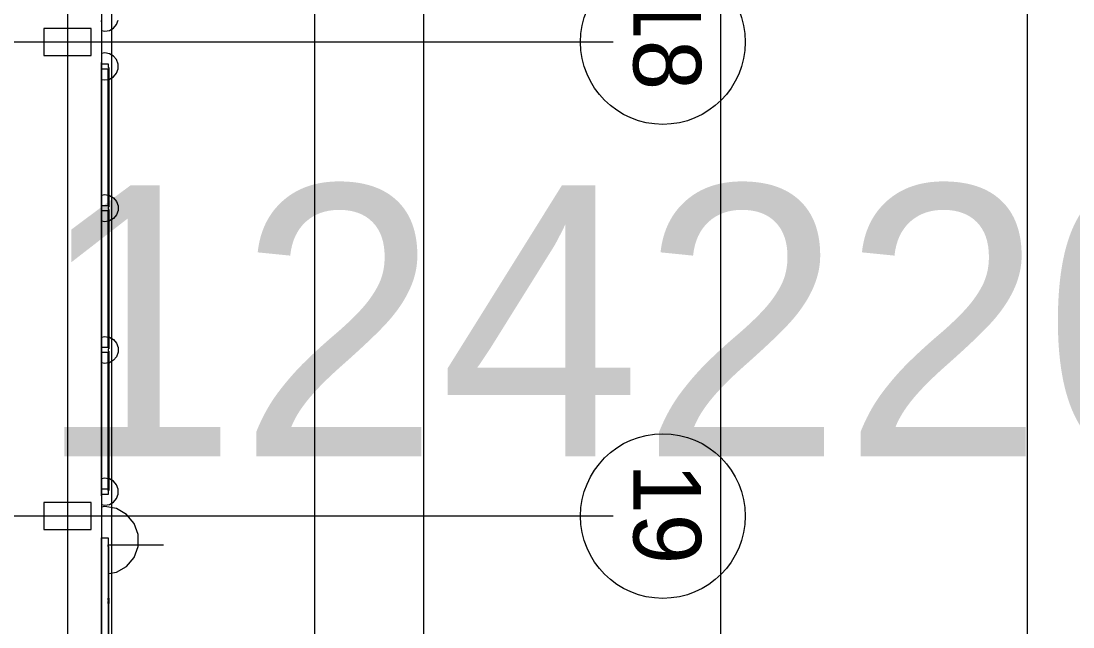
# Model space of a CAD drawing. Extents: x -264165 to -263575, y -1242333 to -1242036.
# Drawn here: x -263796.23 to -263780.69, y -1242204.52 to -1242195.57 of the extents above; entities that cross this region are included whole.
import ezdxf

# ---------------------------------------------------------------- set-up
doc = ezdxf.new("R2010")
doc.units = 0
for name, color, linetype in [('KFA_HEKT_SIET_1-1000', 7, 'Continuous'), ('KFA_HESCON_OSI_STAVBY', 7, 'Continuous'), ('KFA_SITUACIA_DRS_VYTYCOVAK_SEDA', 7, 'Continuous')]:
    doc.layers.add(name, color=color, linetype=linetype)

msp = doc.modelspace()

# ---------------------------------------------------------------- linework, layer by layer
at = {"layer": 'KFA_HESCON_OSI_STAVBY'}
for p, q in [((-263795.543, -1242080.447), (-263795.543, -1242248.737)), ((-263787.486, -1242195.882), (-263921.823, -1242195.882)), ((-263787.486, -1242195.882), (-263787.486, -1242195.882)), ((-263787.486, -1242202.882), (-263921.823, -1242202.882)), ((-263787.486, -1242202.882), (-263787.486, -1242202.882))]:
    msp.add_line(p, q, dxfattribs=at)
for centre in [(-263786.751, -1242195.882), (-263786.751, -1242202.882)]:
    msp.add_circle(centre, 1.216, dxfattribs=at)
at = {"layer": 'KFA_SITUACIA_DRS_VYTYCOVAK_SEDA'}
for p, q in [((-263781.364, -1242208.936), (-263781.371, -1242084.903)), ((-263781.364, -1242208.936), (-263781.371, -1242084.903)), ((-263785.893, -1242228.625), (-263785.893, -1242090.308)), ((-263791.893, -1242228.625), (-263791.893, -1242100.14)), ((-263790.279, -1242228.625), (-263790.279, -1242100.14)), ((-263794.893, -1242101.382), (-263794.893, -1242227.382)), ((-263795.043, -1242188.882), (-263795.043, -1242195.882)), ((-263795.043, -1242188.882), (-263795.043, -1242195.882)), ((-263795.043, -1242195.582), (-263795.043, -1242195.562)), ((-263795.043, -1242195.582), (-263795.043, -1242195.562)), ((-263795.043, -1242195.582), (-263795.043, -1242196.182)), ((-263795.043, -1242195.582), (-263795.043, -1242196.182)), ((-263794.82, -1242195.622), (-263794.796, -1242195.557)), ((-263794.82, -1242195.622), (-263794.796, -1242195.557)), ((-263795.193, -1242195.682), (-263795.893, -1242195.682)), ((-263795.193, -1242195.682), (-263795.893, -1242195.682)), ((-263795.893, -1242195.682), (-263795.893, -1242195.882)), ((-263795.893, -1242195.682), (-263795.893, -1242195.882)), ((-263795.193, -1242195.882), (-263795.193, -1242195.682)), ((-263795.193, -1242195.882), (-263795.193, -1242195.682)), ((-263795.193, -1242195.882), (-263795.193, -1242195.682)), ((-263795.193, -1242195.882), (-263795.193, -1242195.682)), ((-263795.043, -1242195.713), (-263794.993, -1242195.722)), ((-263795.043, -1242195.713), (-263794.993, -1242195.722)), ((-263794.993, -1242195.722), (-263794.924, -1242195.71)), ((-263794.993, -1242195.722), (-263794.924, -1242195.71)), ((-263794.924, -1242195.71), (-263794.864, -1242195.675)), ((-263794.924, -1242195.71), (-263794.864, -1242195.675)), ((-263794.864, -1242195.675), (-263794.82, -1242195.622)), ((-263794.864, -1242195.675), (-263794.82, -1242195.622)), ((-263795.893, -1242195.882), (-263795.893, -1242196.082)), ((-263795.893, -1242195.882), (-263795.893, -1242196.082)), ((-263795.193, -1242196.082), (-263795.193, -1242195.882)), ((-263795.193, -1242196.082), (-263795.193, -1242195.882)), ((-263795.193, -1242196.082), (-263795.193, -1242195.882)), ((-263795.193, -1242196.082), (-263795.193, -1242195.882)), ((-263795.043, -1242195.882), (-263795.043, -1242202.882)), ((-263795.043, -1242195.882), (-263795.043, -1242202.882)), ((-263795.893, -1242196.082), (-263795.193, -1242196.082)), ((-263795.893, -1242196.082), (-263795.193, -1242196.082)), ((-263794.993, -1242196.042), (-263795.043, -1242196.051)), ((-263794.993, -1242196.042), (-263795.043, -1242196.051)), ((-263794.924, -1242196.054), (-263794.993, -1242196.042)), ((-263794.924, -1242196.054), (-263794.993, -1242196.042)), ((-263794.864, -1242196.089), (-263794.924, -1242196.054)), ((-263794.864, -1242196.089), (-263794.924, -1242196.054)), ((-263795.043, -1242196.202), (-263795.043, -1242196.182)), ((-263795.043, -1242196.202), (-263795.043, -1242196.182)), ((-263795.043, -1242196.282), (-263795.043, -1242196.202)), ((-263795.043, -1242196.282), (-263795.043, -1242196.202)), ((-263795.043, -1242196.202), (-263794.943, -1242196.202)), ((-263795.043, -1242196.202), (-263794.943, -1242196.202)), ((-263794.943, -1242196.202), (-263794.943, -1242196.259)), ((-263794.943, -1242196.202), (-263794.943, -1242196.259)), ((-263794.82, -1242196.142), (-263794.864, -1242196.089)), ((-263794.82, -1242196.142), (-263794.864, -1242196.089)), ((-263794.796, -1242196.207), (-263794.82, -1242196.142)), ((-263794.796, -1242196.207), (-263794.82, -1242196.142)), ((-263794.796, -1242196.277), (-263794.796, -1242196.207)), ((-263794.796, -1242196.277), (-263794.796, -1242196.207)), ((-263795.043, -1242198.296), (-263795.043, -1242196.282)), ((-263795.043, -1242198.296), (-263795.043, -1242196.282)), ((-263794.943, -1242196.282), (-263795.043, -1242196.282)), ((-263794.943, -1242196.282), (-263795.043, -1242196.282)), ((-263794.933, -1242196.259), (-263794.943, -1242196.259)), ((-263794.933, -1242196.259), (-263794.943, -1242196.259)), ((-263794.943, -1242198.296), (-263794.943, -1242196.282)), ((-263794.943, -1242198.296), (-263794.943, -1242196.282)), ((-263794.933, -1242196.259), (-263794.933, -1242198.318)), ((-263794.933, -1242196.259), (-263794.933, -1242198.318)), ((-263794.924, -1242196.43), (-263794.864, -1242196.395)), ((-263794.924, -1242196.43), (-263794.864, -1242196.395)), ((-263794.864, -1242196.395), (-263794.82, -1242196.342)), ((-263794.864, -1242196.395), (-263794.82, -1242196.342)), ((-263794.82, -1242196.342), (-263794.796, -1242196.277)), ((-263794.82, -1242196.342), (-263794.796, -1242196.277)), ((-263795.043, -1242196.433), (-263794.993, -1242196.442)), ((-263795.043, -1242196.433), (-263794.993, -1242196.442)), ((-263794.993, -1242196.442), (-263794.943, -1242196.433)), ((-263794.993, -1242196.442), (-263794.943, -1242196.433)), ((-263794.933, -1242196.432), (-263794.924, -1242196.43)), ((-263794.933, -1242196.432), (-263794.924, -1242196.43)), ((-263795.043, -1242198.144), (-263794.993, -1242198.136)), ((-263795.043, -1242198.144), (-263794.993, -1242198.136)), ((-263794.993, -1242198.136), (-263794.943, -1242198.144)), ((-263794.993, -1242198.136), (-263794.943, -1242198.144)), ((-263794.933, -1242198.146), (-263794.924, -1242198.148)), ((-263794.933, -1242198.146), (-263794.924, -1242198.148)), ((-263794.924, -1242198.148), (-263794.864, -1242198.182)), ((-263794.924, -1242198.148), (-263794.864, -1242198.182)), ((-263794.864, -1242198.182), (-263794.82, -1242198.236)), ((-263794.864, -1242198.182), (-263794.82, -1242198.236)), ((-263794.82, -1242198.236), (-263794.796, -1242198.301)), ((-263794.82, -1242198.236), (-263794.796, -1242198.301)), ((-263795.043, -1242198.376), (-263795.043, -1242198.296)), ((-263795.043, -1242198.376), (-263795.043, -1242198.296)), ((-263795.043, -1242198.296), (-263794.943, -1242198.296)), ((-263795.043, -1242198.296), (-263794.943, -1242198.296)), ((-263795.043, -1242200.389), (-263795.043, -1242198.376)), ((-263795.043, -1242200.389), (-263795.043, -1242198.376)), ((-263794.943, -1242198.376), (-263795.043, -1242198.376)), ((-263794.943, -1242198.376), (-263795.043, -1242198.376)), ((-263794.933, -1242198.318), (-263794.943, -1242198.318)), ((-263794.933, -1242198.318), (-263794.943, -1242198.318)), ((-263794.943, -1242198.318), (-263794.943, -1242198.353)), ((-263794.943, -1242198.318), (-263794.943, -1242198.353)), ((-263794.933, -1242198.353), (-263794.943, -1242198.353)), ((-263794.933, -1242198.353), (-263794.943, -1242198.353)), ((-263794.943, -1242200.389), (-263794.943, -1242198.376)), ((-263794.943, -1242200.389), (-263794.943, -1242198.376)), ((-263794.933, -1242198.353), (-263794.933, -1242200.412)), ((-263794.933, -1242198.353), (-263794.933, -1242200.412)), ((-263794.796, -1242198.37), (-263794.82, -1242198.436)), ((-263794.796, -1242198.37), (-263794.82, -1242198.436)), ((-263794.796, -1242198.301), (-263794.796, -1242198.37)), ((-263794.796, -1242198.301), (-263794.796, -1242198.37)), ((-263794.993, -1242198.536), (-263795.043, -1242198.527)), ((-263794.993, -1242198.536), (-263795.043, -1242198.527)), ((-263794.943, -1242198.527), (-263794.993, -1242198.536)), ((-263794.943, -1242198.527), (-263794.993, -1242198.536)), ((-263794.924, -1242198.523), (-263794.933, -1242198.525)), ((-263794.924, -1242198.523), (-263794.933, -1242198.525)), ((-263794.864, -1242198.489), (-263794.924, -1242198.523)), ((-263794.864, -1242198.489), (-263794.924, -1242198.523)), ((-263794.82, -1242198.436), (-263794.864, -1242198.489)), ((-263794.82, -1242198.436), (-263794.864, -1242198.489)), ((-263795.043, -1242200.238), (-263794.993, -1242200.229)), ((-263795.043, -1242200.238), (-263794.993, -1242200.229)), ((-263794.993, -1242200.229), (-263794.943, -1242200.238)), ((-263794.993, -1242200.229), (-263794.943, -1242200.238)), ((-263794.933, -1242200.239), (-263794.924, -1242200.241)), ((-263794.933, -1242200.239), (-263794.924, -1242200.241)), ((-263794.924, -1242200.241), (-263794.864, -1242200.276)), ((-263794.924, -1242200.241), (-263794.864, -1242200.276)), ((-263794.864, -1242200.276), (-263794.82, -1242200.329)), ((-263794.864, -1242200.276), (-263794.82, -1242200.329)), ((-263795.043, -1242200.469), (-263795.043, -1242200.389)), ((-263795.043, -1242200.469), (-263795.043, -1242200.389)), ((-263795.043, -1242200.389), (-263794.943, -1242200.389)), ((-263795.043, -1242200.389), (-263794.943, -1242200.389)), ((-263794.933, -1242200.412), (-263794.943, -1242200.412)), ((-263794.933, -1242200.412), (-263794.943, -1242200.412)), ((-263794.943, -1242200.412), (-263794.943, -1242200.446)), ((-263794.943, -1242200.412), (-263794.943, -1242200.446)), ((-263794.82, -1242200.329), (-263794.796, -1242200.394)), ((-263794.82, -1242200.329), (-263794.796, -1242200.394)), ((-263794.796, -1242200.394), (-263794.796, -1242200.464)), ((-263794.796, -1242200.394), (-263794.796, -1242200.464)), ((-263795.043, -1242202.482), (-263795.043, -1242200.469)), ((-263795.043, -1242202.482), (-263795.043, -1242200.469)), ((-263794.943, -1242200.469), (-263795.043, -1242200.469)), ((-263794.943, -1242200.469), (-263795.043, -1242200.469)), ((-263794.933, -1242200.446), (-263794.943, -1242200.446)), ((-263794.933, -1242200.446), (-263794.943, -1242200.446)), ((-263794.943, -1242202.505), (-263794.943, -1242200.469)), ((-263794.943, -1242202.505), (-263794.943, -1242200.469)), ((-263794.933, -1242200.446), (-263794.933, -1242202.505)), ((-263794.933, -1242200.446), (-263794.933, -1242202.505)), ((-263794.864, -1242200.582), (-263794.924, -1242200.617)), ((-263794.864, -1242200.582), (-263794.924, -1242200.617)), ((-263794.82, -1242200.529), (-263794.864, -1242200.582)), ((-263794.82, -1242200.529), (-263794.864, -1242200.582)), ((-263794.796, -1242200.464), (-263794.82, -1242200.529)), ((-263794.796, -1242200.464), (-263794.82, -1242200.529)), ((-263794.993, -1242200.629), (-263795.043, -1242200.62)), ((-263794.993, -1242200.629), (-263795.043, -1242200.62)), ((-263794.943, -1242200.62), (-263794.993, -1242200.629)), ((-263794.943, -1242200.62), (-263794.993, -1242200.629)), ((-263794.924, -1242200.617), (-263794.933, -1242200.618)), ((-263794.924, -1242200.617), (-263794.933, -1242200.618)), ((-263794.993, -1242202.322), (-263795.043, -1242202.331)), ((-263794.993, -1242202.322), (-263795.043, -1242202.331)), ((-263794.943, -1242202.331), (-263794.993, -1242202.322)), ((-263794.943, -1242202.331), (-263794.993, -1242202.322)), ((-263794.924, -1242202.334), (-263794.933, -1242202.333)), ((-263794.924, -1242202.334), (-263794.933, -1242202.333)), ((-263794.864, -1242202.369), (-263794.924, -1242202.334)), ((-263794.864, -1242202.369), (-263794.924, -1242202.334)), ((-263794.82, -1242202.422), (-263794.864, -1242202.369)), ((-263794.82, -1242202.422), (-263794.864, -1242202.369)), ((-263794.796, -1242202.487), (-263794.82, -1242202.422)), ((-263794.796, -1242202.487), (-263794.82, -1242202.422)), ((-263795.043, -1242202.562), (-263795.043, -1242202.482)), ((-263795.043, -1242202.562), (-263795.043, -1242202.482)), ((-263795.043, -1242202.482), (-263794.943, -1242202.482)), ((-263795.043, -1242202.482), (-263794.943, -1242202.482)), ((-263795.043, -1242202.582), (-263795.043, -1242202.562)), ((-263795.043, -1242202.582), (-263795.043, -1242202.562)), ((-263794.943, -1242202.562), (-263795.043, -1242202.562)), ((-263794.943, -1242202.562), (-263795.043, -1242202.562)), ((-263795.043, -1242202.582), (-263795.043, -1242203.182)), ((-263795.043, -1242202.582), (-263795.043, -1242203.182)), ((-263794.943, -1242202.482), (-263794.943, -1242202.562)), ((-263794.943, -1242202.482), (-263794.943, -1242202.562)), ((-263794.933, -1242202.505), (-263794.943, -1242202.505)), ((-263794.933, -1242202.505), (-263794.943, -1242202.505)), ((-263794.82, -1242202.622), (-263794.796, -1242202.557)), ((-263794.82, -1242202.622), (-263794.796, -1242202.557)), ((-263794.796, -1242202.557), (-263794.796, -1242202.487)), ((-263794.796, -1242202.557), (-263794.796, -1242202.487)), ((-263795.193, -1242202.682), (-263795.893, -1242202.682)), ((-263795.193, -1242202.682), (-263795.893, -1242202.682)), ((-263795.893, -1242202.682), (-263795.893, -1242202.882)), ((-263795.893, -1242202.682), (-263795.893, -1242202.882)), ((-263795.193, -1242202.882), (-263795.193, -1242202.682)), ((-263795.193, -1242202.882), (-263795.193, -1242202.682)), ((-263795.193, -1242202.882), (-263795.193, -1242202.682)), ((-263795.193, -1242202.882), (-263795.193, -1242202.682)), ((-263795.043, -1242202.713), (-263794.993, -1242202.722)), ((-263795.043, -1242202.713), (-263794.993, -1242202.722)), ((-263794.993, -1242202.742), (-263795.043, -1242202.751)), ((-263794.993, -1242202.742), (-263795.043, -1242202.751)), ((-263794.993, -1242202.722), (-263794.924, -1242202.71)), ((-263794.993, -1242202.722), (-263794.924, -1242202.71)), ((-263794.822, -1242202.772), (-263794.993, -1242202.742)), ((-263794.822, -1242202.772), (-263794.993, -1242202.742)), ((-263794.924, -1242202.71), (-263794.864, -1242202.675)), ((-263794.924, -1242202.71), (-263794.864, -1242202.675)), ((-263794.864, -1242202.675), (-263794.82, -1242202.622)), ((-263794.864, -1242202.675), (-263794.82, -1242202.622)), ((-263795.893, -1242202.882), (-263795.893, -1242203.082)), ((-263795.893, -1242202.882), (-263795.893, -1242203.082)), ((-263795.193, -1242203.082), (-263795.193, -1242202.882)), ((-263795.193, -1242203.082), (-263795.193, -1242202.882)), ((-263795.193, -1242203.082), (-263795.193, -1242202.882)), ((-263795.193, -1242203.082), (-263795.193, -1242202.882)), ((-263795.043, -1242202.882), (-263795.043, -1242209.882)), ((-263795.043, -1242202.882), (-263795.043, -1242209.882)), ((-263794.671, -1242202.859), (-263794.822, -1242202.772)), ((-263794.671, -1242202.859), (-263794.822, -1242202.772)), ((-263794.56, -1242202.992), (-263794.671, -1242202.859)), ((-263794.56, -1242202.992), (-263794.671, -1242202.859)), ((-263794.5, -1242203.155), (-263794.56, -1242202.992)), ((-263794.5, -1242203.155), (-263794.56, -1242202.992)), ((-263795.893, -1242203.082), (-263795.193, -1242203.082)), ((-263795.893, -1242203.082), (-263795.193, -1242203.082)), ((-263795.043, -1242203.182), (-263795.043, -1242203.202)), ((-263795.043, -1242203.182), (-263795.043, -1242203.202)), ((-263795.043, -1242205.062), (-263795.043, -1242203.202)), ((-263795.043, -1242205.062), (-263795.043, -1242203.202)), ((-263795.043, -1242203.202), (-263794.943, -1242203.202)), ((-263795.043, -1242203.202), (-263794.943, -1242203.202)), ((-263794.943, -1242203.202), (-263794.943, -1242205.062)), ((-263794.943, -1242203.202), (-263794.943, -1242205.062)), ((-263794.5, -1242203.329), (-263794.5, -1242203.155)), ((-263794.5, -1242203.329), (-263794.5, -1242203.155)), ((-263794.943, -1242203.307), (-263794.128, -1242203.307)), ((-263794.943, -1242203.307), (-263794.128, -1242203.307)), ((-263794.943, -1242203.333), (-263794.943, -1242203.307)), ((-263794.943, -1242203.333), (-263794.943, -1242203.307)), ((-263794.943, -1242203.333), (-263794.933, -1242203.333)), ((-263794.943, -1242203.333), (-263794.933, -1242203.333)), ((-263794.933, -1242204.092), (-263794.933, -1242203.333)), ((-263794.933, -1242204.092), (-263794.933, -1242203.333)), ((-263794.56, -1242203.492), (-263794.5, -1242203.329)), ((-263794.56, -1242203.492), (-263794.5, -1242203.329)), ((-263794.671, -1242203.625), (-263794.56, -1242203.492)), ((-263794.671, -1242203.625), (-263794.56, -1242203.492)), ((-263794.822, -1242203.712), (-263794.671, -1242203.625)), ((-263794.822, -1242203.712), (-263794.671, -1242203.625)), ((-263794.933, -1242203.732), (-263794.822, -1242203.712)), ((-263794.933, -1242203.732), (-263794.822, -1242203.712)), ((-263794.943, -1242204.092), (-263794.933, -1242204.092)), ((-263794.943, -1242204.092), (-263794.933, -1242204.092)), ((-263794.943, -1242204.122), (-263794.943, -1242204.092)), ((-263794.943, -1242204.122), (-263794.943, -1242204.092)), ((-263794.943, -1242204.092), (-263794.933, -1242204.092)), ((-263794.943, -1242204.092), (-263794.933, -1242204.092)), ((-263794.943, -1242204.173), (-263794.943, -1242204.142)), ((-263794.943, -1242204.173), (-263794.943, -1242204.142)), ((-263794.933, -1242204.092), (-263794.933, -1242204.172)), ((-263794.933, -1242204.092), (-263794.933, -1242204.172)), ((-263794.933, -1242204.172), (-263794.943, -1242204.172)), ((-263794.933, -1242204.172), (-263794.943, -1242204.172)), ((-263794.933, -1242204.173), (-263794.943, -1242204.173)), ((-263794.933, -1242204.173), (-263794.943, -1242204.173)), ((-263794.933, -1242204.932), (-263794.933, -1242204.173)), ((-263794.933, -1242204.932), (-263794.933, -1242204.173))]:
    msp.add_line(p, q, dxfattribs=at)

# ---------------------------------------------------------------- texts
at = {"layer": 'KFA_HEKT_SIET_1-1000'}
msp.add_text('1242200', height=4, dxfattribs=at).set_placement((-263796, -1242202))
at = {"layer": 'KFA_HESCON_OSI_STAVBY'}
for s, p in [('18', (-263787.186, -1242195.105)), ('19', (-263787.186, -1242202.105))]:
    msp.add_text(s, height=1, rotation=270, dxfattribs=at).set_placement(p)

doc.saveas('drawing.dxf')
